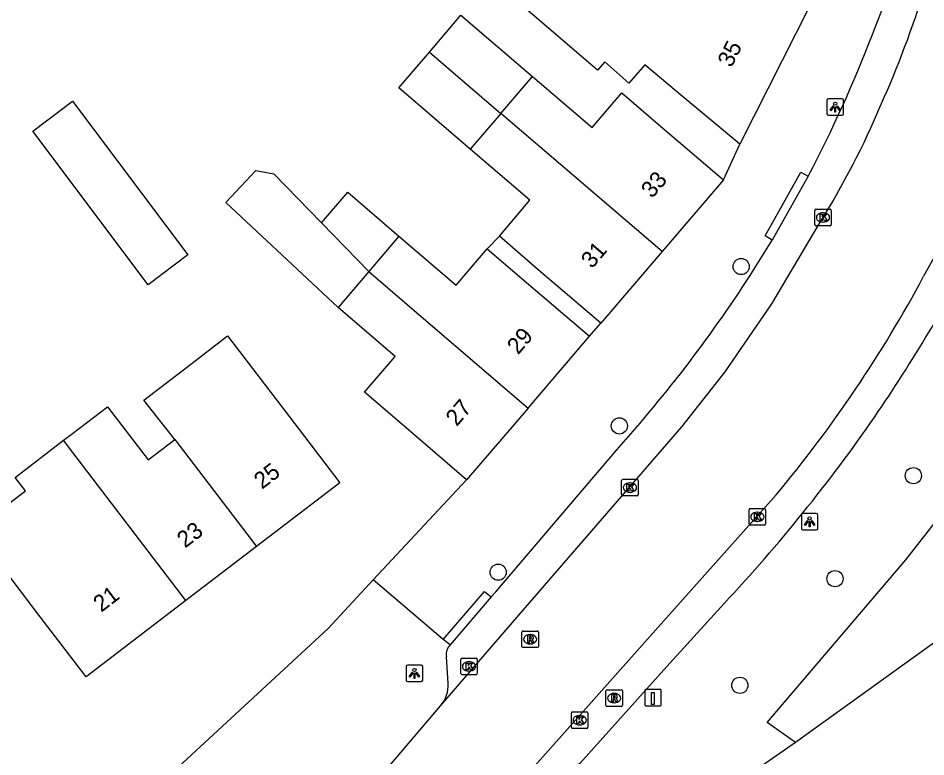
# Model space of a CAD drawing. Extents: x 162880 to 165536, y 384011 to 385179.
# Drawn here: x 164227.5 to 164282.3, y 384340.7 to 384385.3 of the extents above; entities that cross this region are included whole.
import ezdxf

# ---------------------------------------------------------------- set-up
doc = ezdxf.new("R2010")
doc.units = 0
for name, color, linetype in [('IMGEO_Boom', 7, 'Continuous'), ('IMGEO_Groenvoorziening', 7, 'Continuous'), ('IMGEO_Kolk', 7, 'Continuous'), ('IMGEO_Laadpaal', 7, 'Continuous'), ('IMGEO_Lichtpunt', 7, 'Continuous'), ('IMGEO_Pand', 7, 'Continuous'), ('IMGEO_Pand_nummerreeks', 7, 'Continuous'), ('IMGEO_Pand_overbouw', 7, 'Continuous'), ('IMGEO_Rijbaan_lokaal_gesloten', 7, 'Continuous'), ('IMGEO_Rioolput', 7, 'Continuous'), ('IMGEO_Voetpad_open', 7, 'Continuous')]:
    doc.layers.add(name, color=color, linetype=linetype)

msp = doc.modelspace()

# ---------------------------------------------------------------- linework, layer by layer
at = {"layer": 'IMGEO_Boom'}
for centre in [(164271.145, 384370.303), (164263.79, 384360.686), (164281.545, 384357.685), (164256.47, 384351.857), (164276.81, 384351.468), (164271.065, 384345.032)]:
    msp.add_circle(centre, 0.489, dxfattribs=at)
at = {"layer": 'IMGEO_Groenvoorziening'}
msp.add_lwpolyline([(164295.237, 384356.554), (164274.424, 384341.583)], dxfattribs=at)
at = {"layer": 'IMGEO_Kolk'}
for p, q in [((164275.587, 384372.838), (164275.587, 384373.69)), ((164275.662, 384373.764), (164276.514, 384373.764)), ((164276.588, 384373.69), (164276.588, 384372.838)), ((164276.075, 384373.544), (164276.1, 384373.544)), ((164276.514, 384372.764), (164275.662, 384372.764)), ((164276.098, 384372.984), (164276.073, 384372.984)), ((164263.926, 384356.538), (164263.926, 384357.39)), ((164264.001, 384357.464), (164264.853, 384357.464)), ((164264.414, 384357.244), (164264.439, 384357.244)), ((164264.927, 384357.39), (164264.927, 384356.538)), ((164264.437, 384356.684), (164264.412, 384356.684)), ((164264.853, 384356.464), (164264.001, 384356.464)), ((164271.622, 384354.773), (164271.622, 384355.625)), ((164271.697, 384355.699), (164272.549, 384355.699)), ((164272.11, 384355.479), (164272.135, 384355.479)), ((164272.623, 384355.625), (164272.623, 384354.773)), ((164272.133, 384354.919), (164272.108, 384354.919)), ((164272.549, 384354.699), (164271.697, 384354.699)), ((164254.209, 384345.748), (164254.209, 384346.6)), ((164254.284, 384346.674), (164255.136, 384346.674)), ((164254.697, 384346.454), (164254.722, 384346.454)), ((164255.21, 384346.6), (164255.21, 384345.748)), ((164255.136, 384345.674), (164254.284, 384345.674)), ((164254.72, 384345.894), (164254.695, 384345.894)), ((164260.967, 384343.425), (164261.819, 384343.425)), ((164260.892, 384342.499), (164260.892, 384343.351)), ((164261.38, 384343.205), (164261.405, 384343.205)), ((164261.893, 384343.351), (164261.893, 384342.499)), ((164261.819, 384342.425), (164260.967, 384342.425)), ((164261.403, 384342.645), (164261.378, 384342.645))]:
    msp.add_line(p, q, dxfattribs=at)
for points in [[(164275.587, 384372.838), (164275.587, 384373.69)], [(164275.662, 384373.764), (164276.514, 384373.764)], [(164276.588, 384373.69), (164276.588, 384372.838)], [(164275.908, 384373.464), (164276.031, 384373.464), (164276.031, 384373.313), (164276.161, 384373.464), (164276.325, 384373.464), (164276.179, 384373.313), (164276.332, 384373.064), (164276.18, 384373.064), (164276.095, 384373.228), (164276.031, 384373.161), (164276.031, 384373.064), (164275.908, 384373.064), (164275.908, 384373.464)], [(164276.514, 384372.764), (164275.662, 384372.764)], [(164263.926, 384356.538), (164263.926, 384357.39)], [(164264.001, 384357.464), (164264.853, 384357.464)], [(164264.247, 384357.164), (164264.37, 384357.164), (164264.37, 384357.013), (164264.5, 384357.164), (164264.664, 384357.164), (164264.518, 384357.013), (164264.671, 384356.764), (164264.519, 384356.764), (164264.434, 384356.928), (164264.37, 384356.861), (164264.37, 384356.764), (164264.247, 384356.764), (164264.247, 384357.164)], [(164264.927, 384357.39), (164264.927, 384356.538)], [(164264.853, 384356.464), (164264.001, 384356.464)], [(164271.622, 384354.773), (164271.622, 384355.625)], [(164271.697, 384355.699), (164272.549, 384355.699)], [(164272.623, 384355.625), (164272.623, 384354.773)], [(164271.943, 384355.399), (164272.066, 384355.399), (164272.066, 384355.248), (164272.196, 384355.399), (164272.36, 384355.399), (164272.214, 384355.248), (164272.367, 384354.999), (164272.215, 384354.999), (164272.13, 384355.163), (164272.066, 384355.096), (164272.066, 384354.999), (164271.943, 384354.999), (164271.943, 384355.399)], [(164272.549, 384354.699), (164271.697, 384354.699)], [(164254.209, 384345.748), (164254.209, 384346.6)], [(164254.284, 384346.674), (164255.136, 384346.674)], [(164254.53, 384346.374), (164254.653, 384346.374), (164254.653, 384346.223), (164254.783, 384346.374), (164254.947, 384346.374), (164254.801, 384346.223), (164254.954, 384345.974), (164254.802, 384345.974), (164254.717, 384346.138), (164254.653, 384346.071), (164254.653, 384345.974), (164254.53, 384345.974), (164254.53, 384346.374)], [(164255.21, 384346.6), (164255.21, 384345.748)], [(164255.136, 384345.674), (164254.284, 384345.674)], [(164260.967, 384343.425), (164261.819, 384343.425)], [(164260.892, 384342.499), (164260.892, 384343.351)], [(164261.213, 384343.125), (164261.336, 384343.125), (164261.336, 384342.974), (164261.466, 384343.125), (164261.63, 384343.125), (164261.484, 384342.974), (164261.637, 384342.725), (164261.485, 384342.725), (164261.4, 384342.889), (164261.336, 384342.822), (164261.336, 384342.725), (164261.213, 384342.725), (164261.213, 384343.125)], [(164261.893, 384343.351), (164261.893, 384342.499)], [(164261.819, 384342.425), (164260.967, 384342.425)]]:
    msp.add_lwpolyline(points, dxfattribs=at)
for centre, start, end in [((164275.664, 384373.688), 91.552, 178.448), ((164275.664, 384373.688), 91.552, 178.448), ((164276.512, 384373.688), 1.552, 88.448), ((164276.512, 384373.688), 1.552, 88.448), ((164275.664, 384372.84), 181.552, 268.448), ((164275.664, 384372.84), 181.552, 268.448), ((164276.512, 384372.84), 271.552, 358.448), ((164276.512, 384372.84), 271.552, 358.448), ((164264.003, 384357.388), 91.552, 178.448), ((164264.003, 384357.388), 91.552, 178.448), ((164264.851, 384357.388), 1.552, 88.448), ((164264.851, 384357.388), 1.552, 88.448), ((164264.003, 384356.54), 181.552, 268.448), ((164264.003, 384356.54), 181.552, 268.448), ((164264.851, 384356.54), 271.552, 358.448), ((164264.851, 384356.54), 271.552, 358.448), ((164271.699, 384355.623), 91.552, 178.448), ((164271.699, 384355.623), 91.552, 178.448), ((164272.547, 384355.623), 1.552, 88.448), ((164272.547, 384355.623), 1.552, 88.448), ((164271.699, 384354.775), 181.552, 268.448), ((164271.699, 384354.775), 181.552, 268.448), ((164272.547, 384354.775), 271.552, 358.448), ((164272.547, 384354.775), 271.552, 358.448), ((164254.286, 384346.598), 91.552, 178.448), ((164254.286, 384346.598), 91.552, 178.448), ((164255.134, 384346.598), 1.552, 88.448), ((164255.134, 384346.598), 1.552, 88.448), ((164254.286, 384345.75), 181.552, 268.448), ((164254.286, 384345.75), 181.552, 268.448), ((164255.134, 384345.75), 271.552, 358.448), ((164255.134, 384345.75), 271.552, 358.448), ((164260.969, 384343.349), 91.552, 178.448), ((164260.969, 384343.349), 91.552, 178.448), ((164261.817, 384343.349), 1.552, 88.448), ((164261.817, 384343.349), 1.552, 88.448), ((164260.969, 384342.501), 181.552, 268.448), ((164260.969, 384342.501), 181.552, 268.448), ((164261.817, 384342.501), 271.552, 358.448), ((164261.817, 384342.501), 271.552, 358.448)]:
    msp.add_arc(centre, 0.0765, start, end, dxfattribs=at)
for centre, major_axis, ratio, start_param, end_param in [((164276.074, 384373.264), (-0.387, 0.002), 0.722429, 4.712389, 7.853982), ((164276.099, 384373.264), (-0.39, 0.002), 0.717154, 1.570796, 4.712389), ((164264.413, 384356.964), (-0.387, 0.002), 0.722429, 4.712389, 7.853982), ((164264.438, 384356.964), (-0.39, 0.002), 0.717154, 1.570796, 4.712389), ((164272.109, 384355.199), (-0.387, 0.002), 0.722429, 4.712389, 7.853982), ((164272.134, 384355.199), (-0.39, 0.002), 0.717154, 1.570796, 4.712389), ((164254.696, 384346.174), (-0.387, 0.002), 0.722429, 4.712389, 7.853982), ((164254.721, 384346.174), (-0.39, 0.002), 0.717154, 1.570796, 4.712389), ((164261.379, 384342.925), (-0.387, 0.002), 0.722429, 4.712389, 7.853982), ((164261.404, 384342.925), (-0.39, 0.002), 0.717154, 1.570796, 4.712389)]:
    msp.add_ellipse(centre, major_axis=major_axis, ratio=ratio, start_param=start_param, end_param=end_param, dxfattribs=at)
at = {"layer": 'IMGEO_Laadpaal'}
for p, q in [((164265.317, 384344.706), (164265.317, 384343.865)), ((164265.317, 384344.706), (164265.317, 384343.865)), ((164266.233, 384344.79), (164265.392, 384344.79)), ((164266.233, 384344.79), (164265.392, 384344.79)), ((164266.317, 384343.874), (164266.317, 384344.715)), ((164266.317, 384343.874), (164266.317, 384344.715)), ((164265.401, 384343.79), (164266.242, 384343.79)), ((164265.401, 384343.79), (164266.242, 384343.79))]:
    msp.add_line(p, q, dxfattribs=at)
msp.add_lwpolyline([(164265.732, 384344.603), (164265.892, 384344.603), (164265.892, 384343.87), (164265.732, 384343.87), (164265.732, 384344.603)], dxfattribs=at)
for centre, start, end in [((164265.395, 384344.712), 92.4484, 184.2845), ((164265.395, 384344.712), 92.4484, 184.2845), ((164266.239, 384344.712), 2.4484, 94.2845), ((164266.239, 384344.712), 2.4484, 94.2845), ((164265.395, 384343.868), 182.4484, 274.2845), ((164265.395, 384343.868), 182.4484, 274.2845), ((164266.239, 384343.868), 272.4484, 4.2845), ((164266.239, 384343.868), 272.4484, 4.2845)]:
    msp.add_arc(centre, 0.0779, start, end, dxfattribs=at)
at = {"layer": 'IMGEO_Lichtpunt'}
for p, q in [((164276.328, 384380.333), (164276.328, 384379.526)), ((164276.328, 384380.333), (164276.328, 384379.526)), ((164277.23, 384380.428), (164276.422, 384380.428)), ((164277.23, 384380.428), (164276.422, 384380.428)), ((164277.324, 384379.526), (164277.324, 384380.333)), ((164277.324, 384379.526), (164277.324, 384380.333)), ((164276.422, 384379.432), (164277.23, 384379.432)), ((164276.422, 384379.432), (164277.23, 384379.432)), ((164274.78, 384355.308), (164274.78, 384354.501)), ((164274.78, 384355.308), (164274.78, 384354.501)), ((164275.682, 384355.403), (164274.874, 384355.403)), ((164275.682, 384355.403), (164274.874, 384355.403)), ((164275.776, 384354.501), (164275.776, 384355.308)), ((164275.776, 384354.501), (164275.776, 384355.308)), ((164274.874, 384354.407), (164275.682, 384354.407)), ((164274.874, 384354.407), (164275.682, 384354.407)), ((164250.914, 384346.159), (164250.914, 384345.352)), ((164250.914, 384346.159), (164250.914, 384345.352)), ((164251.816, 384346.254), (164251.008, 384346.254)), ((164251.816, 384346.254), (164251.008, 384346.254)), ((164251.91, 384345.352), (164251.91, 384346.159)), ((164251.91, 384345.352), (164251.91, 384346.159)), ((164251.008, 384345.258), (164251.816, 384345.258)), ((164251.008, 384345.258), (164251.816, 384345.258))]:
    msp.add_line(p, q, dxfattribs=at)
for points in [[(164276.702, 384379.997), (164276.741, 384379.969), (164276.553, 384379.707), (164276.515, 384379.734), (164276.702, 384379.997)], [(164276.804, 384379.949), (164276.851, 384379.949), (164276.851, 384379.627), (164276.804, 384379.627), (164276.804, 384379.949)], [(164276.914, 384379.969), (164276.952, 384379.996), (164277.139, 384379.734), (164277.1, 384379.706), (164276.914, 384379.969)], [(164275.154, 384354.972), (164275.193, 384354.944), (164275.005, 384354.682), (164274.967, 384354.709), (164275.154, 384354.972)], [(164275.256, 384354.924), (164275.303, 384354.924), (164275.303, 384354.602), (164275.256, 384354.602), (164275.256, 384354.924)], [(164275.366, 384354.944), (164275.404, 384354.971), (164275.591, 384354.709), (164275.552, 384354.681), (164275.366, 384354.944)], [(164251.288, 384345.823), (164251.327, 384345.795), (164251.139, 384345.533), (164251.101, 384345.56), (164251.288, 384345.823)], [(164251.39, 384345.775), (164251.437, 384345.775), (164251.437, 384345.453), (164251.39, 384345.453), (164251.39, 384345.775)], [(164251.5, 384345.795), (164251.538, 384345.822), (164251.725, 384345.56), (164251.686, 384345.532), (164251.5, 384345.795)]]:
    msp.add_lwpolyline(points, dxfattribs=at)
for centre in [(164276.827, 384380.131), (164275.279, 384355.106), (164251.413, 384345.957)]:
    msp.add_circle(centre, 0.0994, dxfattribs=at)
for centre, start, end in [((164276.422, 384380.333), 90, 180), ((164276.422, 384380.333), 90, 180), ((164277.23, 384380.333), 0, 90), ((164277.23, 384380.333), 0, 90), ((164276.422, 384379.526), 180, 270), ((164276.422, 384379.526), 180, 270), ((164277.23, 384379.526), 270, 0), ((164277.23, 384379.526), 270, 360), ((164274.874, 384355.308), 90, 180), ((164274.874, 384355.308), 90, 180), ((164275.682, 384355.308), 0, 90), ((164275.682, 384355.308), 0, 90), ((164274.874, 384354.501), 180, 270), ((164274.874, 384354.501), 180, 270), ((164275.682, 384354.501), 270, 0), ((164275.682, 384354.501), 270, 360), ((164251.008, 384346.159), 90, 180), ((164251.008, 384346.159), 90, 180), ((164251.816, 384346.159), 0, 90), ((164251.816, 384346.159), 0, 90), ((164251.008, 384345.352), 180, 270), ((164251.008, 384345.352), 180, 270), ((164251.816, 384345.352), 270, 0), ((164251.816, 384345.352), 270, 360)]:
    msp.add_arc(centre, 0.0946, start, end, dxfattribs=at)
at = {"layer": 'IMGEO_Pand'}
for points in [[(164271.057, 384377.691), (164267.216, 384380.891), (164265.32, 384382.471), (164264.358, 384381.377), (164262.911, 384382.649), (164262.476, 384382.154), (164236.314, 384404.571), (164243.286, 384405.608)], [(164275.297, 384386.032), (164271.057, 384377.691)], [(164252.316, 384383.243), (164254.223, 384385.472), (164258.542, 384381.777)], [(164254.784, 384377.384), (164250.465, 384381.078), (164252.316, 384383.243)], [(164252.316, 384383.243), (164256.632, 384379.544)], [(164256.632, 384379.544), (164258.542, 384381.777)], [(164258.542, 384381.777), (164262.145, 384378.695), (164263.93, 384380.782), (164266.271, 384378.778), (164270.07, 384375.527)], [(164228.366, 384378.477), (164230.763, 384380.275), (164237.719, 384371.004), (164235.323, 384369.205), (164228.366, 384378.477)], [(164256.632, 384379.544), (164254.784, 384377.384)], [(164266.367, 384371.201), (164260.233, 384376.458), (164256.632, 384379.544)], [(164262.667, 384366.877), (164258.888, 384370.111), (164256.543, 384372.144), (164258.388, 384374.301), (164254.784, 384377.384)], [(164246.799, 384367.836), (164240.031, 384374.169), (164241.831, 384376.093), (164242.919, 384375.89), (164245.801, 384372.934)], [(164270.07, 384375.527), (164266.367, 384371.201)], [(164245.801, 384372.934), (164247.382, 384374.782), (164250.477, 384372.133)], [(164245.801, 384372.934), (164248.656, 384370.005)], [(164250.477, 384372.133), (164248.656, 384370.005)], [(164250.477, 384372.133), (164253.93, 384369.178), (164255.809, 384371.373), (164258.178, 384369.345), (164261.977, 384366.094)], [(164266.367, 384371.201), (164262.667, 384366.877)], [(164248.656, 384370.005), (164246.799, 384367.836)], [(164248.656, 384370.005), (164252.106, 384367.048), (164258.271, 384361.764)], [(164254.565, 384357.434), (164250.766, 384360.685), (164248.397, 384362.714), (164250.251, 384364.881), (164246.799, 384367.836)], [(164236.939, 384359.863), (164235.07, 384362.248), (164237.721, 384364.275), (164240.129, 384366.117), (164243.868, 384361.228), (164246.906, 384357.256), (164241.876, 384353.409)], [(164258.271, 384361.764), (164261.977, 384366.094)], [(164230.218, 384359.816), (164230.752, 384360.224), (164232.874, 384361.846), (164235.331, 384358.633), (164236.939, 384359.863)], [(164258.271, 384361.764), (164254.565, 384357.434)], [(164236.939, 384359.863), (164241.876, 384353.409)], [(164237.612, 384350.148), (164231.582, 384345.535), (164228.545, 384349.507), (164224.828, 384354.41), (164227.92, 384356.767), (164227.296, 384357.583), (164230.218, 384359.816)], [(164237.612, 384350.148), (164230.845, 384358.996), (164230.218, 384359.816)], [(164241.876, 384353.409), (164237.612, 384350.148)]]:
    msp.add_lwpolyline(points, dxfattribs=at)
at = {"layer": 'IMGEO_Pand_overbouw'}
msp.add_lwpolyline([(164261.977, 384366.094), (164262.667, 384366.877), (164258.888, 384370.111), (164256.543, 384372.144), (164255.809, 384371.373), (164258.178, 384369.345)], close=True, dxfattribs=at)
at = {"layer": 'IMGEO_Rijbaan_lokaal_gesloten'}
for points in [[(164290.958, 384391.829), (164289.066, 384384.974), (164285.827, 384376.709), (164284.485, 384373.867), (164282.166, 384369.713)], [(164253.005, 384343.806), (164257.723, 384349.267), (164267.553, 384360.623), (164270.174, 384363.948), (164273.004, 384368.053), (164275.89, 384372.942)], [(164273.26, 384356.536), (164265.969, 384348.359), (164258.038, 384339.442)], [(164241.966, 384330.855), (164253.005, 384343.806)]]:
    msp.add_lwpolyline(points, dxfattribs=at)
for centre, radius, start, end in [((164223.121, 384405.367), 61.878, 335.89315, 342.78004), ((164232.446, 384400.029), 51.197, 328.0564, 337.0836), ((164213.099, 384406.795), 78.392, 320.12405, 331.76843)]:
    msp.add_arc(centre, radius, start, end, dxfattribs=at)
at = {"layer": 'IMGEO_Rioolput'}
for p, q in [((164257.903, 384347.384), (164257.903, 384348.236)), ((164257.978, 384348.31), (164258.83, 384348.31)), ((164258.391, 384348.09), (164258.416, 384348.09)), ((164258.904, 384348.236), (164258.904, 384347.384)), ((164258.83, 384347.31), (164257.978, 384347.31)), ((164258.414, 384347.53), (164258.389, 384347.53)), ((164262.971, 384343.838), (164262.971, 384344.69)), ((164263.046, 384344.764), (164263.898, 384344.764)), ((164263.459, 384344.544), (164263.484, 384344.544)), ((164263.972, 384344.69), (164263.972, 384343.838)), ((164263.482, 384343.984), (164263.457, 384343.984)), ((164263.898, 384343.764), (164263.046, 384343.764))]:
    msp.add_line(p, q, dxfattribs=at)
for points in [[(164257.903, 384347.384), (164257.903, 384348.236)], [(164257.978, 384348.31), (164258.83, 384348.31)], [(164258.492, 384348.008), (164258.24, 384348.01), (164258.24, 384347.61)], [(164258.418, 384347.929), (164258.364, 384347.929), (164258.364, 384347.848)], [(164258.364, 384347.848), (164258.416, 384347.848)], [(164258.904, 384348.236), (164258.904, 384347.384)], [(164258.83, 384347.31), (164257.978, 384347.31)], [(164258.24, 384347.61), (164258.364, 384347.61), (164258.364, 384347.772), (164258.375, 384347.772)], [(164258.422, 384347.743), (164258.493, 384347.61), (164258.633, 384347.61), (164258.568, 384347.736)], [(164262.971, 384343.838), (164262.971, 384344.69)], [(164263.046, 384344.764), (164263.898, 384344.764)], [(164263.972, 384344.69), (164263.972, 384343.838)], [(164263.56, 384344.462), (164263.308, 384344.464), (164263.308, 384344.064)], [(164263.308, 384344.064), (164263.432, 384344.064), (164263.432, 384344.226), (164263.443, 384344.226)], [(164263.486, 384344.383), (164263.432, 384344.383), (164263.432, 384344.302)], [(164263.432, 384344.302), (164263.484, 384344.302)], [(164263.49, 384344.197), (164263.561, 384344.064), (164263.701, 384344.064), (164263.636, 384344.19)], [(164263.898, 384343.764), (164263.046, 384343.764)]]:
    msp.add_lwpolyline(points, dxfattribs=at)
for centre, radius, start, end in [((164257.98, 384348.234), 0.0765, 91.552, 178.448), ((164257.98, 384348.234), 0.0765, 91.552, 178.448), ((164258.4, 384348.037), 0.19, 274.7715, 282.9687), ((164258.424, 384347.833), 0.0964, 77.0061, 93.1865), ((164258.438, 384347.89), 0.0378, 276.6634, 79.6772), ((164258.491, 384347.898), 0.109, 350.3612, 89.416), ((164258.489, 384347.898), 0.112, 277.5842, 350.9817), ((164258.473, 384347.683), 0.108, 29.5134, 73.7905), ((164258.828, 384348.234), 0.0765, 1.552, 88.448), ((164258.828, 384348.234), 0.0765, 1.552, 88.448), ((164257.98, 384347.386), 0.0765, 181.552, 268.448), ((164257.98, 384347.386), 0.0765, 181.552, 268.448), ((164258.374, 384347.719), 0.0533, 26.0293, 88.6989), ((164258.828, 384347.386), 0.0765, 271.552, 358.448), ((164258.828, 384347.386), 0.0765, 271.552, 358.448), ((164263.048, 384344.688), 0.0765, 91.552, 178.448), ((164263.048, 384344.688), 0.0765, 91.552, 178.448), ((164263.896, 384344.688), 0.0765, 1.552, 88.448), ((164263.896, 384344.688), 0.0765, 1.552, 88.448), ((164263.442, 384344.173), 0.0533, 26.0293, 88.6989), ((164263.468, 384344.491), 0.19, 274.7715, 282.9687), ((164263.492, 384344.287), 0.0964, 77.0061, 93.1865), ((164263.506, 384344.344), 0.0378, 276.6634, 79.6772), ((164263.559, 384344.352), 0.109, 350.3612, 89.416), ((164263.557, 384344.352), 0.112, 277.5842, 350.9817), ((164263.541, 384344.137), 0.108, 29.5134, 73.7905), ((164263.048, 384343.84), 0.0765, 181.552, 268.448), ((164263.048, 384343.84), 0.0765, 181.552, 268.448), ((164263.896, 384343.84), 0.0765, 271.552, 358.448), ((164263.896, 384343.84), 0.0765, 271.552, 358.448)]:
    msp.add_arc(centre, radius, start, end, dxfattribs=at)
for centre, major_axis, ratio, start_param, end_param in [((164258.39, 384347.81), (-0.387, 0.002), 0.722429, 4.712389, 7.853982), ((164258.415, 384347.81), (-0.39, 0.002), 0.717154, 1.570796, 4.712389), ((164263.458, 384344.264), (-0.387, 0.002), 0.722429, 4.712389, 7.853982), ((164263.483, 384344.264), (-0.39, 0.002), 0.717154, 1.570796, 4.712389)]:
    msp.add_ellipse(centre, major_axis=major_axis, ratio=ratio, start_param=start_param, end_param=end_param, dxfattribs=at)
at = {"layer": 'IMGEO_Voetpad_open'}
for points in [[(164270.07, 384375.527), (164271.057, 384377.691)], [(164273.019, 384371.903), (164272.584, 384372.149), (164274.756, 384376.002), (164275.191, 384375.756)], [(164275.191, 384375.756), (164273.019, 384371.903)], [(164271.912, 384370.116), (164273.019, 384371.903)], [(164261.977, 384366.094), (164262.667, 384366.877)], [(164274.424, 384341.583), (164272.712, 384342.789), (164281.086, 384352.605), (164286.999, 384360.158), (164288.245, 384362.997)], [(164256.046, 384350.382), (164256.319, 384350.664), (164263.637, 384359.251)], [(164248.925, 384351.39), (164254.565, 384357.434)], [(164230.475, 384333.944), (164246.201, 384348.47), (164248.925, 384351.39)], [(164253.152, 384347.804), (164248.925, 384351.39)], [(164253.152, 384347.804), (164255.649, 384350.692), (164256.046, 384350.382)], [(164256.046, 384350.382), (164253.572, 384347.474)], [(164270.119, 384349.978), (164266.65, 384346.167), (164261.396, 384340.319), (164260.801, 384339.919), (164259.016, 384339.795)], [(164253.572, 384347.474), (164253.152, 384347.804)], [(164253.451, 384345.134), (164253.347, 384346.768)], [(164274.424, 384341.583), (164268.257, 384337.301), (164268.366, 384337.124), (164260.84, 384329.156), (164251.674, 384320.699), (164245.639, 384315.799), (164245.34, 384316.175), (164244.454, 384315.55), (164241.784, 384302.243), (164241.621, 384301.03)]]:
    msp.add_lwpolyline(points, dxfattribs=at)
for centre, radius, start, end in [((164217.448, 384409.096), 66.421, 338.08049, 352.60398), ((164205.303, 384412.609), 79.01, 332.19687, 339.00517), ((164198.31, 384416.62), 98.045, 325.60865, 332.64034), ((164201.046, 384415.505), 84.155, 318.05206, 327.3607), ((164198.944, 384416.783), 97.615, 316.8142, 325.31982), ((164254.079, 384346.924), 0.748, 132.6346, 192.0116), ((164251.514, 384345.046), 1.939, 320.2619, 2.6095)]:
    msp.add_arc(centre, radius, start, end, dxfattribs=at)

# ---------------------------------------------------------------- texts
at = {"layer": 'IMGEO_Pand_nummerreeks'}
for s, rotation, p in [('35', 63.054, (164270.556, 384382.267)), ('33', 49.4405, (164265.767, 384374.375)), ('31', 49.4405, (164262.139, 384370.136)), ('29', 49.4405, (164257.672, 384364.94)), ('27', 49.4405, (164253.966, 384360.61)), ('25', 37.4141, (164242.204, 384356.833)), ('23', 37.4116, (164237.557, 384353.279)), ('21', 37.4116, (164232.499, 384349.41))]:
    msp.add_text(s, height=1, rotation=rotation, dxfattribs=at).set_placement(p)

doc.saveas('drawing.dxf')
